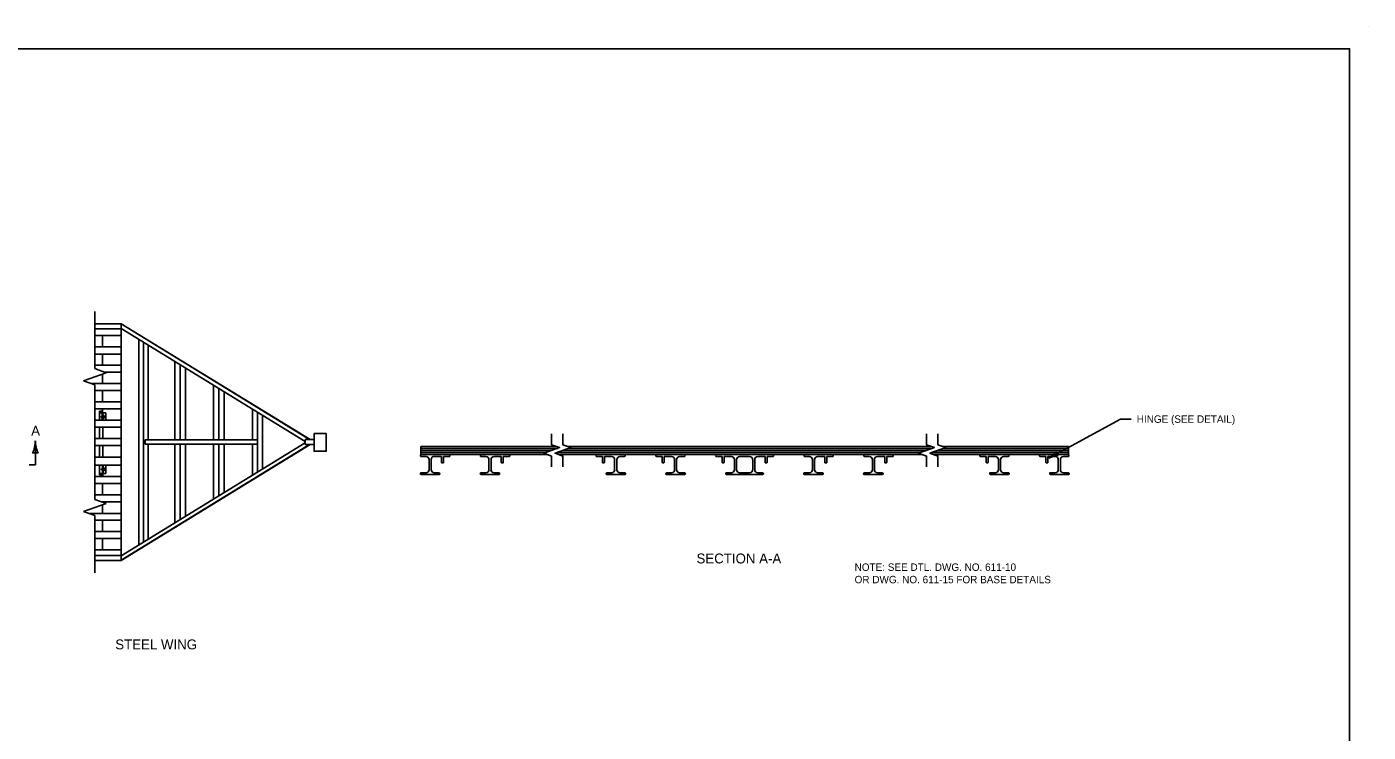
# Model space of a CAD drawing. Extents: x 49991.4 to 50021, y 49987.6 to 50011.4.
# Drawn here: x 50006.08 to 50016.9, y 49993.49 to 49999.18 of the extents above; entities that cross this region are included whole.
import ezdxf

# ---------------------------------------------------------------- set-up
doc = ezdxf.new("R2010")
doc.units = 0
for name, color, linetype in [('Level 1', 7, 'Continuous'), ('Level 2', 7, 'Continuous'), ('Level 3', 7, 'Continuous'), ('Level 4', 7, 'Continuous'), ('Level 6', 7, 'Continuous')]:
    doc.layers.add(name, color=color, linetype=linetype)

msp = doc.modelspace()

# ---------------------------------------------------------------- linework, layer by layer
at = {"layer": 'Level 1'}
for p, q in [((50016.9, 49999.176), (50016.9, 49999.176)), ((50006.631, 49996.781), (50006.845, 49996.781)), ((50006.845, 49996.781), (50008.368, 49995.847)), ((50006.845, 49996.781), (50006.845, 49994.872)), ((50006.631, 49996.741), (50006.845, 49996.741)), ((50006.845, 49996.685), (50006.631, 49996.685)), ((50006.695, 49996.594), (50006.695, 49996.685)), ((50006.845, 49996.742), (50008.329, 49995.831)), ((50006.987, 49996.655), (50006.987, 49994.998)), ((50006.845, 49996.594), (50006.631, 49996.594)), ((50007.024, 49996.633), (50007.024, 49995.02)), ((50007.063, 49996.608), (50007.063, 49995.844)), ((50006.631, 49996.536), (50006.845, 49996.536)), ((50006.631, 49996.446), (50006.845, 49996.446)), ((50006.695, 49996.446), (50006.695, 49996.536)), ((50007.278, 49996.477), (50007.278, 49995.844)), ((50007.32, 49996.45), (50007.32, 49995.844)), ((50006.695, 49996.299), (50006.695, 49996.376)), ((50006.713, 49996.39), (50006.845, 49996.39)), ((50007.363, 49996.424), (50007.363, 49995.844)), ((50006.604, 49996.299), (50006.845, 49996.299)), ((50006.631, 49996.242), (50006.845, 49996.242)), ((50006.695, 49996.151), (50006.695, 49996.242)), ((50007.59, 49996.285), (50007.59, 49995.844)), ((50007.633, 49996.259), (50007.633, 49995.844)), ((50007.676, 49996.233), (50007.676, 49995.844)), ((50006.631, 49996.151), (50006.845, 49996.151)), ((50006.631, 49996.094), (50006.845, 49996.094)), ((50006.631, 49996.003), (50006.845, 49996.003)), ((50006.695, 49996.075), (50006.669, 49996.075)), ((50006.669, 49996.003), (50006.669, 49996.075)), ((50006.721, 49996.063), (50006.669, 49996.063)), ((50006.692, 49996.034), (50006.683, 49996.034)), ((50006.683, 49996.034), (50006.683, 49996.026)), ((50006.683, 49996.026), (50006.692, 49996.026)), ((50006.692, 49996.063), (50006.692, 49996.003)), ((50006.695, 49996.094), (50006.695, 49996.003)), ((50006.698, 49996.063), (50006.698, 49996.003)), ((50006.707, 49996.041), (50006.698, 49996.041)), ((50006.707, 49996.034), (50006.698, 49996.034)), ((50006.707, 49996.026), (50006.698, 49996.026)), ((50006.707, 49996.019), (50006.698, 49996.019)), ((50006.707, 49996.041), (50006.707, 49996.019)), ((50006.721, 49996.063), (50006.721, 49996.003)), ((50007.903, 49996.093), (50007.903, 49995.844)), ((50007.943, 49996.069), (50007.943, 49995.584)), ((50007.983, 49996.044), (50007.983, 49995.609)), ((50006.631, 49995.946), (50006.845, 49995.946)), ((50006.67, 49995.855), (50006.67, 49995.946)), ((50006.696, 49995.855), (50006.696, 49995.946)), ((50006.631, 49995.855), (50006.845, 49995.855)), ((50006.631, 49995.799), (50006.845, 49995.799)), ((50006.67, 49995.706), (50006.67, 49995.799)), ((50006.696, 49995.706), (50006.696, 49995.799)), ((50006.845, 49994.91), (50008.329, 49995.821)), ((50006.845, 49994.872), (50008.368, 49995.806)), ((50007.037, 49995.844), (50007.943, 49995.844)), ((50007.037, 49995.844), (50007.037, 49995.809)), ((50007.037, 49995.809), (50007.943, 49995.809)), ((50007.063, 49995.809), (50007.063, 49995.044)), ((50007.278, 49995.809), (50007.278, 49995.176)), ((50007.32, 49995.809), (50007.32, 49995.202)), ((50007.363, 49995.809), (50007.363, 49995.228)), ((50007.59, 49995.809), (50007.59, 49995.368)), ((50007.633, 49995.809), (50007.633, 49995.394)), ((50007.676, 49995.809), (50007.676, 49995.42)), ((50007.903, 49995.809), (50007.903, 49995.559)), ((50009.262, 49995.727), (50009.262, 49995.792)), ((50009.262, 49995.792), (50010.352, 49995.792)), ((50010.443, 49995.792), (50013.374, 49995.792)), ((50014.483, 49995.792), (50013.465, 49995.792)), ((50014.483, 49995.727), (50014.483, 49995.792)), ((50006.631, 49995.706), (50006.845, 49995.706)), ((50009.262, 49995.776), (50010.362, 49995.776)), ((50009.262, 49995.76), (50010.316, 49995.76)), ((50009.262, 49995.743), (50010.27, 49995.743)), ((50009.262, 49995.727), (50010.281, 49995.727)), ((50009.262, 49995.726), (50009.493, 49995.726)), ((50009.262, 49995.71), (50009.303, 49995.71)), ((50009.328, 49995.685), (50009.328, 49995.604)), ((50009.344, 49995.604), (50009.344, 49995.685)), ((50009.369, 49995.71), (50009.427, 49995.71)), ((50009.427, 49995.71), (50009.427, 49995.661)), ((50009.444, 49995.661), (50009.444, 49995.71)), ((50009.444, 49995.71), (50009.493, 49995.71)), ((50009.745, 49995.726), (50009.975, 49995.726)), ((50009.745, 49995.71), (50009.786, 49995.71)), ((50009.81, 49995.685), (50009.81, 49995.604)), ((50009.827, 49995.604), (50009.827, 49995.685)), ((50009.851, 49995.71), (50009.91, 49995.71)), ((50009.91, 49995.71), (50009.91, 49995.661)), ((50009.926, 49995.661), (50009.926, 49995.71)), ((50009.926, 49995.71), (50009.975, 49995.71)), ((50010.361, 49995.743), (50013.293, 49995.743)), ((50010.372, 49995.727), (50013.303, 49995.727)), ((50010.407, 49995.76), (50013.339, 49995.76)), ((50010.453, 49995.776), (50013.385, 49995.776)), ((50010.906, 49995.726), (50010.676, 49995.726)), ((50010.725, 49995.71), (50010.676, 49995.71)), ((50010.725, 49995.661), (50010.725, 49995.71)), ((50010.8, 49995.71), (50010.741, 49995.71)), ((50010.741, 49995.71), (50010.741, 49995.661)), ((50010.824, 49995.604), (50010.824, 49995.685)), ((50010.841, 49995.685), (50010.841, 49995.604)), ((50010.906, 49995.71), (50010.866, 49995.71)), ((50011.389, 49995.726), (50011.159, 49995.726)), ((50011.208, 49995.71), (50011.159, 49995.71)), ((50011.208, 49995.661), (50011.208, 49995.71)), ((50011.283, 49995.71), (50011.224, 49995.71)), ((50011.224, 49995.71), (50011.224, 49995.661)), ((50011.307, 49995.604), (50011.307, 49995.685)), ((50011.324, 49995.685), (50011.324, 49995.604)), ((50011.389, 49995.71), (50011.348, 49995.71)), ((50011.641, 49995.726), (50012.102, 49995.726)), ((50011.69, 49995.71), (50011.641, 49995.71)), ((50011.69, 49995.661), (50011.69, 49995.71)), ((50011.765, 49995.71), (50011.707, 49995.71)), ((50011.707, 49995.71), (50011.707, 49995.661)), ((50011.79, 49995.604), (50011.79, 49995.685)), ((50011.806, 49995.685), (50011.806, 49995.604)), ((50011.912, 49995.71), (50011.831, 49995.71)), ((50011.937, 49995.685), (50011.937, 49995.604)), ((50011.954, 49995.604), (50011.954, 49995.686)), ((50011.978, 49995.71), (50012.037, 49995.71)), ((50012.037, 49995.71), (50012.037, 49995.661)), ((50012.053, 49995.661), (50012.053, 49995.71)), ((50012.053, 49995.71), (50012.102, 49995.71)), ((50012.354, 49995.726), (50012.584, 49995.726)), ((50012.354, 49995.71), (50012.395, 49995.71)), ((50012.419, 49995.685), (50012.419, 49995.604)), ((50012.436, 49995.604), (50012.436, 49995.686)), ((50012.461, 49995.71), (50012.519, 49995.71)), ((50012.519, 49995.71), (50012.519, 49995.661)), ((50012.536, 49995.661), (50012.536, 49995.71)), ((50012.536, 49995.71), (50012.585, 49995.71)), ((50012.837, 49995.726), (50013.067, 49995.726)), ((50012.837, 49995.71), (50012.877, 49995.71)), ((50012.902, 49995.685), (50012.902, 49995.604)), ((50012.919, 49995.604), (50012.919, 49995.686)), ((50012.943, 49995.71), (50013.002, 49995.71)), ((50013.002, 49995.71), (50013.002, 49995.661)), ((50013.018, 49995.661), (50013.018, 49995.71)), ((50013.018, 49995.71), (50013.067, 49995.71)), ((50014.483, 49995.743), (50013.384, 49995.743)), ((50014.483, 49995.727), (50013.394, 49995.727)), ((50014.483, 49995.76), (50013.43, 49995.76)), ((50014.483, 49995.776), (50013.476, 49995.776)), ((50014.001, 49995.726), (50013.771, 49995.726)), ((50013.819, 49995.71), (50013.771, 49995.71)), ((50013.819, 49995.661), (50013.819, 49995.71)), ((50013.895, 49995.71), (50013.836, 49995.71)), ((50013.836, 49995.71), (50013.836, 49995.661)), ((50013.919, 49995.604), (50013.919, 49995.686)), ((50013.936, 49995.686), (50013.936, 49995.604)), ((50014.001, 49995.71), (50013.96, 49995.71)), ((50014.483, 49995.726), (50014.253, 49995.726)), ((50014.302, 49995.71), (50014.253, 49995.71)), ((50014.302, 49995.661), (50014.302, 49995.71)), ((50014.377, 49995.71), (50014.318, 49995.71)), ((50014.318, 49995.71), (50014.318, 49995.661)), ((50014.401, 49995.604), (50014.401, 49995.686)), ((50014.418, 49995.686), (50014.418, 49995.604)), ((50014.483, 49995.71), (50014.443, 49995.71)), ((50006.631, 49995.64), (50006.845, 49995.64)), ((50006.67, 49995.64), (50006.67, 49995.562)), ((50006.722, 49995.574), (50006.67, 49995.574)), ((50006.685, 49995.603), (50006.685, 49995.61)), ((50006.685, 49995.61), (50006.693, 49995.61)), ((50006.693, 49995.603), (50006.685, 49995.603)), ((50006.693, 49995.574), (50006.693, 49995.64)), ((50006.696, 49995.549), (50006.696, 49995.64)), ((50006.699, 49995.574), (50006.699, 49995.64)), ((50006.708, 49995.618), (50006.699, 49995.618)), ((50006.708, 49995.611), (50006.699, 49995.611)), ((50006.708, 49995.602), (50006.699, 49995.602)), ((50006.708, 49995.595), (50006.699, 49995.595)), ((50006.708, 49995.595), (50006.708, 49995.618)), ((50006.722, 49995.574), (50006.722, 49995.64)), ((50009.263, 49995.579), (50009.303, 49995.579)), ((50009.41, 49995.579), (50009.369, 49995.579)), ((50009.745, 49995.579), (50009.786, 49995.579)), ((50009.893, 49995.579), (50009.852, 49995.579)), ((50010.759, 49995.579), (50010.8, 49995.579)), ((50010.906, 49995.579), (50010.866, 49995.579)), ((50011.241, 49995.579), (50011.283, 49995.579)), ((50011.389, 49995.579), (50011.348, 49995.579)), ((50011.724, 49995.579), (50011.765, 49995.579)), ((50011.912, 49995.579), (50011.831, 49995.579)), ((50012.02, 49995.58), (50011.978, 49995.58)), ((50012.355, 49995.579), (50012.395, 49995.579)), ((50012.502, 49995.58), (50012.461, 49995.58)), ((50012.837, 49995.579), (50012.878, 49995.579)), ((50012.985, 49995.58), (50012.943, 49995.58)), ((50013.853, 49995.58), (50013.894, 49995.58)), ((50014, 49995.579), (50013.96, 49995.579)), ((50014.335, 49995.58), (50014.377, 49995.58)), ((50014.483, 49995.579), (50014.443, 49995.579)), ((50006.631, 49995.549), (50006.845, 49995.549)), ((50006.631, 49995.492), (50006.845, 49995.492)), ((50006.696, 49995.562), (50006.67, 49995.562)), ((50006.695, 49995.401), (50006.695, 49995.492)), ((50009.262, 49995.565), (50009.411, 49995.565)), ((50009.744, 49995.565), (50009.894, 49995.565)), ((50010.758, 49995.565), (50010.907, 49995.565)), ((50011.24, 49995.565), (50011.39, 49995.565)), ((50011.723, 49995.565), (50012.02, 49995.565)), ((50012.354, 49995.565), (50012.503, 49995.565)), ((50012.836, 49995.565), (50012.985, 49995.565)), ((50013.852, 49995.565), (50014.001, 49995.566)), ((50014.335, 49995.566), (50014.484, 49995.566)), ((50006.631, 49995.401), (50006.845, 49995.401)), ((50006.582, 49995.252), (50006.845, 49995.252)), ((50006.687, 49995.344), (50006.845, 49995.344)), ((50006.695, 49995.252), (50006.695, 49995.322)), ((50006.631, 49995.197), (50006.845, 49995.197)), ((50006.695, 49995.197), (50006.695, 49995.105)), ((50006.631, 49995.105), (50006.845, 49995.105)), ((50006.631, 49995.048), (50006.845, 49995.048)), ((50006.695, 49994.958), (50006.695, 49995.048)), ((50006.631, 49994.958), (50006.845, 49994.958)), ((50006.631, 49994.912), (50006.845, 49994.912)), ((50006.631, 49994.872), (50006.844, 49994.872)), ((50006.844, 49994.872), (50006.845, 49994.872))]:
    msp.add_line(p, q, dxfattribs=at)
for points in [[(49999.384, 49998.999), (50016.75, 49998.999), (50016.75, 49987.799), (49999.384, 49987.799)], [(50008.4, 49995.895), (50008.4, 49995.753), (50008.499, 49995.753), (50008.499, 49995.895)], [(50008.329, 49995.847), (50008.329, 49995.806), (50008.4, 49995.806), (50008.4, 49995.847)]]:
    msp.add_lwpolyline(points, close=True, dxfattribs=at)
for centre, radius, start, end in [((50009.303, 49995.685), 0.0245, 0.1309, 90.1308), ((50009.367, 49995.688), 0.0225, 85.0314, 185.3256), ((50009.786, 49995.685), 0.0245, 0.1309, 90.1308), ((50009.851, 49995.686), 0.0235, 88.0071, 182.3499), ((50010.801, 49995.687), 0.0231, 356.4913, 93.1517), ((50010.866, 49995.685), 0.0245, 89.8692, 179.8692), ((50011.284, 49995.687), 0.0228, 355.5982, 94.0447), ((50011.348, 49995.685), 0.0245, 89.8692, 179.8692), ((50011.766, 49995.686), 0.0237, 358.1433, 91.4997), ((50011.831, 49995.685), 0.0245, 89.8692, 179.8692), ((50011.912, 49995.685), 0.0245, 0.1309, 90.1308), ((50011.977, 49995.686), 0.0237, 88.3061, 182.0509), ((50012.395, 49995.685), 0.0245, 0.1309, 90.1308), ((50012.459, 49995.687), 0.0227, 85.6929, 184.6641), ((50012.878, 49995.685), 0.0245, 0.1309, 90.1308), ((50012.942, 49995.687), 0.0234, 87.6491, 182.7079), ((50013.896, 49995.687), 0.023, 356.1633, 93.4797), ((50013.96, 49995.685), 0.0245, 89.8692, 179.8692), ((50014.378, 49995.687), 0.0233, 356.9743, 92.6686), ((50014.443, 49995.685), 0.0245, 89.8692, 179.8692), ((50009.303, 49995.604), 0.0245, 270.1309, 0.1308), ((50009.369, 49995.604), 0.0245, 180.1309, 270.1309), ((50009.786, 49995.604), 0.0245, 270.1309, 0.1308), ((50009.851, 49995.604), 0.0245, 180.1309, 270.1309), ((50010.8, 49995.604), 0.0245, 269.8691, 359.8691), ((50010.866, 49995.604), 0.0245, 179.8691, 269.8691), ((50011.283, 49995.604), 0.0245, 269.8691, 359.8691), ((50011.348, 49995.604), 0.0245, 179.8691, 269.8691), ((50011.765, 49995.604), 0.0245, 269.8691, 359.8691), ((50011.831, 49995.604), 0.0245, 179.8691, 269.8691), ((50011.912, 49995.604), 0.0245, 270.1309, 0.1308), ((50011.978, 49995.604), 0.0245, 180.1309, 270.1309), ((50012.395, 49995.604), 0.0245, 270.1309, 0.1308), ((50012.461, 49995.604), 0.0245, 180.1309, 270.1309), ((50012.878, 49995.604), 0.0245, 270.1309, 0.1308), ((50012.943, 49995.604), 0.0245, 180.1309, 270.1309), ((50013.894, 49995.604), 0.0245, 269.8691, 359.8691), ((50013.96, 49995.604), 0.0245, 179.8691, 269.8691), ((50014.377, 49995.604), 0.0245, 269.8691, 359.8691), ((50014.443, 49995.604), 0.0245, 179.8691, 269.8691)]:
    msp.add_arc(centre, radius, start, end, dxfattribs=at)
for centre, major_axis, ratio, start_param, end_param in [((50009.262, 49995.718), (-0.00002, 0.00817), 0.356754, 0, 3.141593), ((50009.493, 49995.718), (0.00002, -0.00817), 0.392805, 0, 3.141593), ((50009.745, 49995.718), (-0.00002, 0.00817), 0.356754, 0, 3.141593), ((50009.975, 49995.718), (0.00002, -0.00817), 0.392805, 0, 3.141593), ((50010.676, 49995.718), (-0.00002, -0.00817), 0.392805, 3.141593, 6.283185), ((50010.906, 49995.718), (0.00002, 0.00817), 0.356754, 3.141593, 6.283185), ((50011.159, 49995.718), (-0.00002, -0.00817), 0.392805, 3.141593, 6.283185), ((50011.389, 49995.718), (0.00002, 0.00817), 0.356754, 3.141593, 6.283185), ((50011.641, 49995.718), (-0.00002, -0.00817), 0.392805, 3.141593, 6.283185), ((50012.102, 49995.718), (0.00002, -0.00817), 0.392805, 0, 3.141593), ((50012.354, 49995.718), (-0.00002, 0.00817), 0.356754, 0, 3.141593), ((50012.584, 49995.718), (0.00002, -0.00817), 0.392805, 0, 3.141593), ((50012.837, 49995.718), (-0.00002, 0.00817), 0.356754, 0, 3.141593), ((50013.067, 49995.718), (0.00002, -0.00817), 0.392805, 0, 3.141593), ((50013.771, 49995.718), (-0.00002, -0.00817), 0.392805, 3.141593, 6.283185), ((50014.001, 49995.718), (0.00002, 0.00817), 0.356754, 3.141593, 6.283185), ((50014.253, 49995.718), (-0.00002, -0.00817), 0.392805, 3.141593, 6.283185), ((50014.483, 49995.718), (0.00002, 0.00817), 0.356754, 3.141593, 6.283185), ((50009.263, 49995.572), (-0.00025, 0.00695), 0.928868, 0, 2.919512), ((50009.41, 49995.572), (-0.00003, -0.00717), 0.534325, 0.187696, 3.141593), ((50009.436, 49995.661), (-0.00817, -0.00002), 0.234187, 0, 3.141593), ((50009.746, 49995.572), (-0.00025, 0.00695), 0.928868, 0, 2.919512), ((50009.893, 49995.572), (-0.00003, -0.00717), 0.534325, 0.187696, 3.141593), ((50009.918, 49995.661), (-0.00817, -0.00002), 0.234187, 0, 3.141593), ((50010.733, 49995.661), (0.00817, -0.00002), 0.234187, 3.141593, 6.283185), ((50010.759, 49995.572), (0.00003, -0.00717), 0.534325, 3.141593, 6.076715), ((50010.906, 49995.572), (0.00025, 0.00695), 0.928868, 3.382741, 6.283185), ((50011.216, 49995.661), (0.00817, -0.00002), 0.234187, 3.141593, 6.283185), ((50011.241, 49995.572), (0.00003, -0.00717), 0.534325, 3.141593, 6.076713), ((50011.388, 49995.572), (0.00025, 0.00695), 0.928868, 3.382741, 6.283185), ((50011.698, 49995.661), (0.00817, -0.00002), 0.234187, 3.141593, 6.283185), ((50011.724, 49995.572), (0.00003, -0.00717), 0.534325, 3.141593, 6.043934), ((50012.02, 49995.572), (-0.00003, -0.00717), 0.534325, 0.146109, 3.141593), ((50012.045, 49995.661), (-0.00817, -0.00002), 0.234187, 0, 3.141593), ((50012.355, 49995.572), (-0.00025, 0.00695), 0.928868, 0, 2.951883), ((50012.502, 49995.572), (-0.00003, -0.00717), 0.534325, 0.161043, 3.141593), ((50012.527, 49995.661), (-0.00817, -0.00002), 0.234187, 0, 3.141593), ((50012.837, 49995.572), (-0.00025, 0.00695), 0.928868, 0, 2.93527), ((50012.985, 49995.572), (-0.00003, -0.00717), 0.534325, 0.176923, 3.141593), ((50013.01, 49995.661), (-0.00817, -0.00002), 0.234187, 0, 3.141593), ((50013.828, 49995.661), (0.00817, -0.00002), 0.234187, 3.141593, 6.283185), ((50013.853, 49995.573), (0.00003, -0.00717), 0.534325, 3.141593, 6.095489), ((50014, 49995.572), (0.00025, 0.00695), 0.928868, 3.382741, 6.283185), ((50014.31, 49995.661), (0.00817, -0.00002), 0.234187, 3.141593, 6.283185), ((50014.336, 49995.573), (0.00003, -0.00717), 0.534325, 3.141593, 6.039934), ((50014.483, 49995.572), (0.00025, 0.00695), 0.928868, 3.435164, 6.283185)]:
    msp.add_ellipse(centre, major_axis=major_axis, ratio=ratio, start_param=start_param, end_param=end_param, dxfattribs=at)
at = {"layer": 'Level 3'}
for p in [(50014.326, 49995.697), (50014.989, 49996.012)]:
    msp.add_line(p, (50014.904, 49996.012), dxfattribs=at)
for centre, radius, start, end in [((50014.204, 49995.896), 0.233, 301.4653, 320.7151), ((50014.424, 49995.498), 0.222, 96.094, 116.2775), ((50014.439, 49995.758), 0.0548, 190.7768, 226.4992)]:
    msp.add_arc(centre, radius, start, end, dxfattribs=at)
at = {"layer": 'Level 4'}
for p, q in [((50006.845, 49996.779), (50008.364, 49995.847)), ((50006.845, 49994.874), (50008.364, 49995.806))]:
    msp.add_line(p, q, dxfattribs=at)
at = {"layer": 'Level 6'}
for p, q in [((50006.631, 49996.419), (50006.631, 49996.881)), ((50006.631, 49996.354), (50006.54, 49996.321)), ((50006.723, 49996.386), (50006.631, 49996.419)), ((50006.723, 49996.386), (50006.631, 49996.354)), ((50006.631, 49996.289), (50006.54, 49996.321)), ((50006.631, 49995.364), (50006.631, 49996.289)), ((50006.153, 49995.642), (50006.153, 49995.838)), ((50006.153, 49995.642), (50006.104, 49995.642)), ((50006.723, 49995.331), (50006.631, 49995.364)), ((50006.631, 49995.299), (50006.54, 49995.267)), ((50006.631, 49995.234), (50006.54, 49995.267)), ((50006.723, 49995.331), (50006.631, 49995.299)), ((50006.631, 49994.772), (50006.631, 49995.234))]:
    msp.add_line(p, q, dxfattribs=at)
for points in [[(50010.316, 49995.627), (50010.316, 49995.714), (50010.252, 49995.737), (50010.38, 49995.782), (50010.316, 49995.805), (50010.316, 49995.892)], [(50010.407, 49995.627), (50010.407, 49995.714), (50010.343, 49995.737), (50010.471, 49995.782), (50010.407, 49995.805), (50010.407, 49995.892)], [(50013.339, 49995.627), (50013.339, 49995.714), (50013.275, 49995.737), (50013.403, 49995.782), (50013.339, 49995.805), (50013.339, 49995.892)], [(50013.43, 49995.627), (50013.43, 49995.714), (50013.366, 49995.737), (50013.494, 49995.782), (50013.43, 49995.805), (50013.43, 49995.892)]]:
    msp.add_lwpolyline(points, dxfattribs=at)
for centre, radius, start, end in [((50005.857, 49995.85), 0.296, 337.456, 357.6395), ((50006.463, 49995.853), 0.311, 182.8273, 202.0772), ((50006.153, 49995.667), 0.073, 72.1388, 107.8612)]:
    msp.add_arc(centre, radius, start, end, dxfattribs=at)

# ---------------------------------------------------------------- texts
at = {"layer": 'Level 2'}
for s, height, p in [('HINGE (SEE DETAIL)', 0.06, (50015.034, 49995.982)), ('A', 0.08, (50006.119, 49995.878)), ('SECTION A-A', 0.08, (50011.484, 49994.848)), ('NOTE: SEE DTL. DWG. NO. 611-10 ', 0.06, (50012.759, 49994.788)), ('OR DWG. NO. 611-15 FOR BASE DETAILS', 0.06, (50012.759, 49994.688)), ('STEEL WING', 0.08, (50006.797, 49994.155))]:
    msp.add_text(s, height=height, dxfattribs=at).set_placement(p)

doc.saveas('drawing.dxf')
